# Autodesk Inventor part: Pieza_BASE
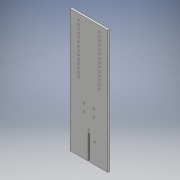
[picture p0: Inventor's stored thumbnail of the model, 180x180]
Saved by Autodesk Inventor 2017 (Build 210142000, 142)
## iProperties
Part Number: Pieza_BASE
Material: Genérico
Document SubType Name: Modeling
Designer: Jaime
Density: 1 g/cm^3
Appearance: Valor por defecto
Author: Jaime
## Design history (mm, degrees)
sketch "Boceto1"
  geometry: L1 (100, 325)-(-100, 325); L2 (-100, 325)-(-100, -325); L3 (-100, -325)-(100, -325); L4 (100, -325)-(100, 325); 3 further points
  constraints: 8 end point, 2 midpoint, 2 parallel, 1 horizontal, 1 horizontal alignment, 1 perpendicular, 1 vertical alignment
  dimensions: "d0" = 650 distance of L3.end L1.start; "d1" = 200 distance of L1.start L1.end
extrude "Extrusión1" new body sketch "Boceto1" distance "d2" = 10; taper "d3" = 0 deg
sketch "Boceto2"
  geometry: L1 (-5, 325)-(5, 325); L2 (5, 325)-(5, 195); L3 (5, 195)-(-5, 195); L4 (-5, 195)-(-5, 325); L5 (100, 325)-(-100, 325) reference; 3 further points
  constraints: 8 end point, 3 midpoint, 2 parallel, 1 coincident, 1 horizontal, 1 perpendicular
  dimensions: "d4" = 10 distance of L2.end L3.end; "d5" = 130 distance of L3.end L1.start
extrude "Extrusión2" cut sketch "Boceto2" stored distance "d6" = 10; taper "d7" = 0 deg
sketch "Boceto3"
  geometry: L1 (-100, -325)-(100, -325) reference; L2 (-100, 325)-(-100, -325) reference; L3 (5, 195)-(-5, 195) reference; C1 r 4 at (-55, -295); C2 r 4 at (55, -295); C3 r 4 at (-55, -275); C4 r 4 at (55, -275); C5 r 4 at (-55, -255); C6 r 4 at (55, -255); C7 r 4 at (-55, -235); C8 r 4 at (55, -235); C9 r 4 at (-55, -215); C10 r 4 at (55, -215); C11 r 4 at (-55, -195); C12 r 4 at (55, -195); C13 r 4 at (-55, -175); C14 r 4 at (55, -175); C15 r 4 at (-55, -155); C16 r 4 at (55, -155); C17 r 4 at (-55, -135); C18 r 4 at (55, -135); C19 r 4 at (-55, -115); C20 r 4 at (55, -115); C21 r 4 at (-55, -95); C22 r 4 at (55, -95); C23 r 4 at (-55, -75); C24 r 4 at (55, -75); C25 r 4 at (-55, -55); C26 r 4 at (55, -55); C27 r 4 at (-55, -35); C28 r 4 at (55, -35); C29 r 4 at (-25, 70); C30 r 4 at (-25, 110); C31 r 4 at (25, 70); C32 r 4 at (25, 110); C33 r 4 at (0, 180); C34 r 4 at (30, 220); 1 further point
  constraints: 34 centre point, 2 horizontal alignment, 2 vertical alignment, 1 horizontal, 1 vertical, 54 other
  dimensions: "d8" = 8 diameter of C1; "d9" = 55 horizontal distance of point (0, 0) C1.centre; "d10" = 30 distance from line of C1.centre L1; "d13" = 110 distance of C1.centre C2.centre; "d16" = 20 distance of C1.centre C3.centre; "d19" = 395 distance from line of L1 C29.centre; "d20" = 25 horizontal distance of point (0, 0) C29.centre; "d21" = 8 diameter of C29; "d22" = 8 diameter of C30; "d23" = 8 diameter of C31; "d24" = 8 diameter of C32; "d25" = 50 distance of C31.centre C29.centre; "d26" = 40 distance of C30.centre C29.centre; "d27" = 40 distance of C32.centre C31.centre; "d28" = 8 diameter of C33; "d29" = 15 distance from line of L3 C33.centre; "d30" = 8 diameter of C34; "d31" = 40 vertical distance of C34.centre C33.centre; "d32" = 30 horizontal distance of C33.centre C34.centre
extrude "Extrusión3" cut sketch "Boceto3" stored distance "d33" = 10; taper "d34" = 0 deg
node "Sólido1"
